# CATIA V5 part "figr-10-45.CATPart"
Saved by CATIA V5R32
Part number: Part1
Bounding box of the stored display mesh (mm): x -20 to 20, y -41.679 to 32.292, z -5.268 to 19.6
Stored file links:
  D:\PROJECTS\Project 2022\CATIA V5 6R 2022\Resources\Part Files\c10_catia_v5_6r2022_prt\c10_catia_v5_6r2022_prt\figr-10-45.CATPart
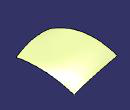
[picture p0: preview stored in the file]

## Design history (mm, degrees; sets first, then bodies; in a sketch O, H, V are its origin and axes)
Set1
  Plane1: type Offset, RefPlane yz-plane, Offset 20, reversed
  Plane2: type Offset, RefPlane yz-plane, Offset 20
  Sketch1 on Plane1, origin (-20, 0, 0), H (0, 1, 0), V (0, 0, 1)
    spline S1 through (-41.3356, 3.6998) (10.9718, 19.5196) (47.9697, 8.2926)
  Sketch2 on yz-plane, origin (0, 0, 0), H (0, 1, 0), V (0, 0, 1)
    spline S1 through (-41.087, 1.981) (-29.2011, 1.8342) (-9.0978, 3.8886) (28.3207, 0)
    point P1 (28.3207, 0)
    coincidence: P1 H
  Sketch3 on Plane2, origin (20, 0, 0), H (0, 1, 0), V (0, 0, 1)
    spline S1 through (-41.7094, -2.237) (-14.4323, 0.9381) (25.2566, -5.2678)
  Plane3: type Offset, RefPlane yz-plane, Offset 10
  Sketch4 on Plane3, origin (10, 0, 0), H (0, 1, 0), V (0, 0, 1)
    spline S1 through (-45.2274, 0) (26.2784, 6.3461) (36.8255, 3.6647)
    point P1 (-45.2274, 0)
    coincidence: P1 H
  Sweep1: type Conic, Guide ({sweepconicextendedguide Guide Sketch1, Reference Sketch2, Angle 15}; {sweepconicextendedguide Guide Sketch3, Reference Sketch4, Angle 0}), Parameter 0.5
Body1 (main body)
